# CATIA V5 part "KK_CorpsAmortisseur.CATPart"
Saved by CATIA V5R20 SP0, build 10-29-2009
Part number: Corps amortisseur
Bounding box of the stored display mesh (mm): x -256 to 256, y 512 to 1440, z -2196 to -96.115
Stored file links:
  G:\Khaled_CFAO_2011\ST2M\ST2M_GR2\aboulegue\Khaled\CAD_thinkMOTION\KK_CorpsAmortisseur.CATPart
  G:\Khaled_CFAO_2011\ST2M\ST2M_GR2\aboulegue\Khaled\CAD_thinkMOTION\KK_Train_Atterrissage.CATProduct
  G:\Khaled_CFAO_2011\ST2M\ST2M_GR2\aboulegue\Khaled\CAD_thinkMOTION\KK_Squelette_TigeAmortisseur.CATPart
  G:\Khaled_CFAO_2011\ST2M\ST2M_GR2\aboulegue\Khaled\CAD_thinkMOTION\KK_SquelettePanneau_Pivotant.CATPart
  G:\Khaled_CFAO_2011\ST2M\ST2M_GR2\aboulegue\Khaled\CAD_thinkMOTION\KK_Squelette_Amortisseur.CATPart
  G:\Khaled_CFAO_2011\ST2M\ST2M_GR2\aboulegue\CFAO_aboulegue\CFAO_aboulegue_fichiers_catia\Compas superieur.CATPart
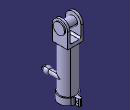
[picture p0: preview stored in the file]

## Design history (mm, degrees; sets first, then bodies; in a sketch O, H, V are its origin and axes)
External parameters (linked from other documents)
  `External.Longueur corps d'amortisseur` = 1780 mm
  `External.hauteur panneau pivotant` = 1280 mm
Set1
  Plane1 "Plan reference": linked copy from another document
  Line1: linked copy from another document
  Point1 "Point.14": linked copy from another document
  Point2: linked copy from another document
  Line2 to Line5: linked copy from another document
  Point3 "Point.18": linked copy from another document
  Plane2 "Plan corps amortisseur": linked copy from another document
  Line6: linked copy from another document
  Line7: linked copy from another document
  Point4: linked copy from another document
  Line8: linked copy from another document
  Point5: linked copy from another document
Body1 (main body)
  Sketch1 on Plane1, origin (0, 0, 0), H (0, 1, 0), V (0, 0, 1)
    line L1 (1056, -756) -> (1056, -2196)
    line L2 (1056, -2196) -> (1312, -2196)
    line L3 (1312, -2196) -> (1312, -2004)
    line L4 (1312, -2004) -> (1280, -2004)
    line L5 (1280, -2004) -> (1280, -756)
    line L6 (1280, -756) -> (1056, -756)
    reference projected line E1 (1056, -864) -> (1056, -3072) from Line1
    reference projected line E2 (1376, -2100) -> (1056, -2100) from Line8
    reference projected line E3 (1376, -2100) -> (1056, -2100) from Line8
    distance L5 L1 = 224
    length L4 = 32
    length L1 = 1440
    distance E2 L2 = 96
    distance E3 L4 = 96
    vertical: L1 V, L3 V, L5 V
    horizontal: L2 H, L4 H, L6 H
    coincidence: L1 E1
  Shaft1: profile Sketch1, axis Sketch1.L1, angle 360
  Sketch2 on Plane1, origin (0, 0, 0), H (0, 1, 0), V (0, 0, 1)
    line L1 (832, -756) -> (832, -320)
    arc A1 centre (1056, -320) radius 224 from (832, -320) to (1280, -320) cw
    line L2 (1280, -320) -> (1280, -756)
    line L3 (1280, -756) -> (832, -756)
    reference projected point E1 (1056, -320) from Point3
    reference projected line E2 (1264, -756) -> (848, -756) from Sketch3.L4
    distance L3 E2 = 0
    distance L2 L1 = 448
    vertical: L1 V
    tangency: A1 L1, L2 A1
    horizontal: L3 H
    concentricity: E1 A1
  Sketch3 on face of Shaft1 from Sketch1.L6, origin (0, 0, -756), H (1, 0, 0), V (0, 1, 0)
    line L1 (-224, 1280) -> (224, 1280)
    line L2 (224, 1280) -> (224, 832)
    line L3 (224, 832) -> (-224, 832)
    line L4 (-224, 832) -> (-224, 1280)
    reference projected line E1 (0, 768) -> (0, 1312) from Line4
    reference projected line E2 (-200, 1056) -> (200, 1056) from Line5
    length L2 = 448
    length L3 = 448
    distance E1 L2 = 224
    distance E2 L1 = 224
    horizontal: L1 H, L3 H
    vertical: L2 V, L4 V
  SolidCombine1: FirstComponentProfile Sketch2, FirstComponentDirection Sketch2, SecondComponentProfile Sketch3, SecondComponentDirection Sketch3
  Sketch4 on face of SolidCombine1 from Sketch3.L1, origin (0, 1280, 0), H (-1, 0, 0), V (0, 0, 1)
    line L1 (-157, -56) -> (157, -56)
    line L2 (157, -56) -> (157, -656)
    line L3 (157, -656) -> (-157, -656)
    line L4 (-157, -656) -> (-157, -56)
    reference projected line E1 (-224, -320) -> (-224, -112) from edge [face of SolidCombine1 from Sketch2.A1 | face of SolidCombine1 from Sketch3.L2]
    reference projected line E2 (208, -756) -> (-208, -756) from edge [face of SolidCombine1 from Sketch3.L1 | face of SolidCombine1 from Sketch2.L3]
    length L1 = 314
    distance L4 E1 = 67
    distance E2 L3 = 100
    length L2 = 600
    horizontal: L1 H, L3 H
    vertical: L2 V, L4 V
  Pocket1: profile Sketch4, direction (0, -1, 0), through (limit type 6)
  Fillet1: radius 50, on edge [face of Pocket1 from Sketch4.L2 | face of Pocket1 from Sketch4.L3]; edge [face of Pocket1 from Sketch4.L3 | face of Pocket1 from Sketch4.L4]
  Sketch5 on Plane2, origin (160, 0, 0), H (0, 1, 0), V (0, 0, 1)
    line L1 (512, -1536) -> (1056, -1536)
    line L2 (1056, -1536) -> (1056, -1600)
    line L3 (1056, -1600) -> (512, -1600)
    line L4 (512, -1600) -> (512, -1536)
    point P4 (512, -1600)
    reference projected line E1 (1056, -320) -> (1056, -2100) from Line6
    reference projected line E2 (1056, -1600) -> (736, -1600) from Line7
    reference projected point E3 (640, -1600) from Point4
    length L4 = 64
    distance E3 P4 = 128
    horizontal: L1 H, L3 H
    vertical: L2 V, L4 V
    coincidence: E1 L2, E2 L3
  Shaft2: profile Sketch5, axis Sketch5.L3, angle 360
  Sketch6 on Plane2, origin (160, 0, 0), H (0, 1, 0), V (0, 0, 1)
    arc A1 centre (640, -1600) radius 96 from (736, -1600) to (544, -1600) ccw
    point P1 (640, -1600)
    reference projected point E1 (640, -1600) from Point4
    line L1 (544, -1600) -> (736, -1600)
    point P2 (736, -1600)
    point P4 (736, -1600)
    radius A1 = 96
    coincidence: E1 P1, P2 A1, P2 P4
    horizontal: L1 H
  Shaft3: profile Sketch6, axis Sketch6.L1, angle 360
  Sketch7 on face of Shaft1 from Sketch1.L2, origin (0, 0, -2196), H (1, 0, 0), V (0, -1, 0)
    circle A1 centre (0, -1056) radius 160
    point P1 (0, -1056)
    reference projected point E1 (0, -1056) from Point1
    radius A1 = 160
    coincidence: E1 P1
  Pocket2: profile Sketch7, direction (0, 0, 1), length 1332 {= `External.Longueur corps d'amortisseur` -448mm}
  Sketch8 on Plane1, origin (0, 0, 0), H (0, 1, 0), V (0, 0, 1)
    line L1 (1280, -2004) -> (1440, -2004)
    line L2 (1440, -2004) -> (1440, -2196)
    line L3 (1440, -2196) -> (1280, -2196)
    line L4 (1280, -2196) -> (1280, -2004)
    reference projected line E1 (1376, -2100) -> (1056, -2100) from Line8
    reference projected line E2 through (1056, 0) direction (0, -1) from axis of face of Shaft1 from Sketch1.L5
    length L2 = 192
    distance E1 L1 = 96
    distance E2 L4 = 224
    length L3 = 160
    horizontal: L1 H, L3 H
    vertical: L2 V, L4 V
  Pad1: profile Sketch8, direction (1, 0, 0), length 48, mirrored extent
  Fillet2: radius 20, on edge [face of Shaft1 from Sketch1.L3 | end face of Pad1]; edge [start face of Pad1 | face of Shaft1 from Sketch1.L3]
  Fillet3: radius 30, on edge [face of Pad1 from Sketch8.L2 | end face of Pad1]; edge [start face of Pad1 | face of Pad1 from Sketch8.L2]
  Sketch9 on end face of Pad1, origin (48, 0, 0), H (0, 1, 0), V (0, 0, 1)
    circle A1 centre (1376, -2100) radius 32
    point P1 (1376, -2100)
    reference projected point E1 (1376, -2100) from Point5
    radius A1 = 32
    coincidence: E1 P1
  Pocket3: profile Sketch9, direction (-1, 0, 0), through (limit type 6)
  Fillet4: radius 20, on edge [face of Shaft2 from Sketch5.L4 | face of Shaft2 from Sketch5.L1]
  Sketch10 on face of SolidCombine1 from Sketch3.L2, origin (224, 0, 0), H (0, 1, 0), V (0, 0, 1)
    circle A1 centre (1056, -320) radius 128
    point P1 (1056, -320)
    reference projected point E1 (1056, -320) from Point2
    radius A1 = 128
    coincidence: E1 P1
  Pocket4: profile Sketch10, direction (-1, 0, 0), through (limit type 3)
  Sketch11 on face of SolidCombine1 from Sketch3.L2, origin (224, 0, 0), H (0, 1, 0), V (0, 0, 1)
    circle A1 centre (1056, -320) radius 160
    point P1 (1056, -320)
    reference projected point E1 (1056, -320) from Point2
    radius A1 = 160
    coincidence: E1 P1
  Pad2: profile Sketch11, direction (1, 0, 0), length 32
  Sketch12 on start face of Pad2, origin (224, 0, 0), H (0, -1, 0), V (0, 0, 1)
    circle A1 centre (-1056, -320) radius 128
    reference projected circle E1 centre (-1056, -320) radius 128 from edge [start face of Pad2 | face of Pocket4 from Sketch10.A1]
    coincidence: A1 E1
  Pad3: profile Sketch12, direction (-1, 0, 0), length 480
